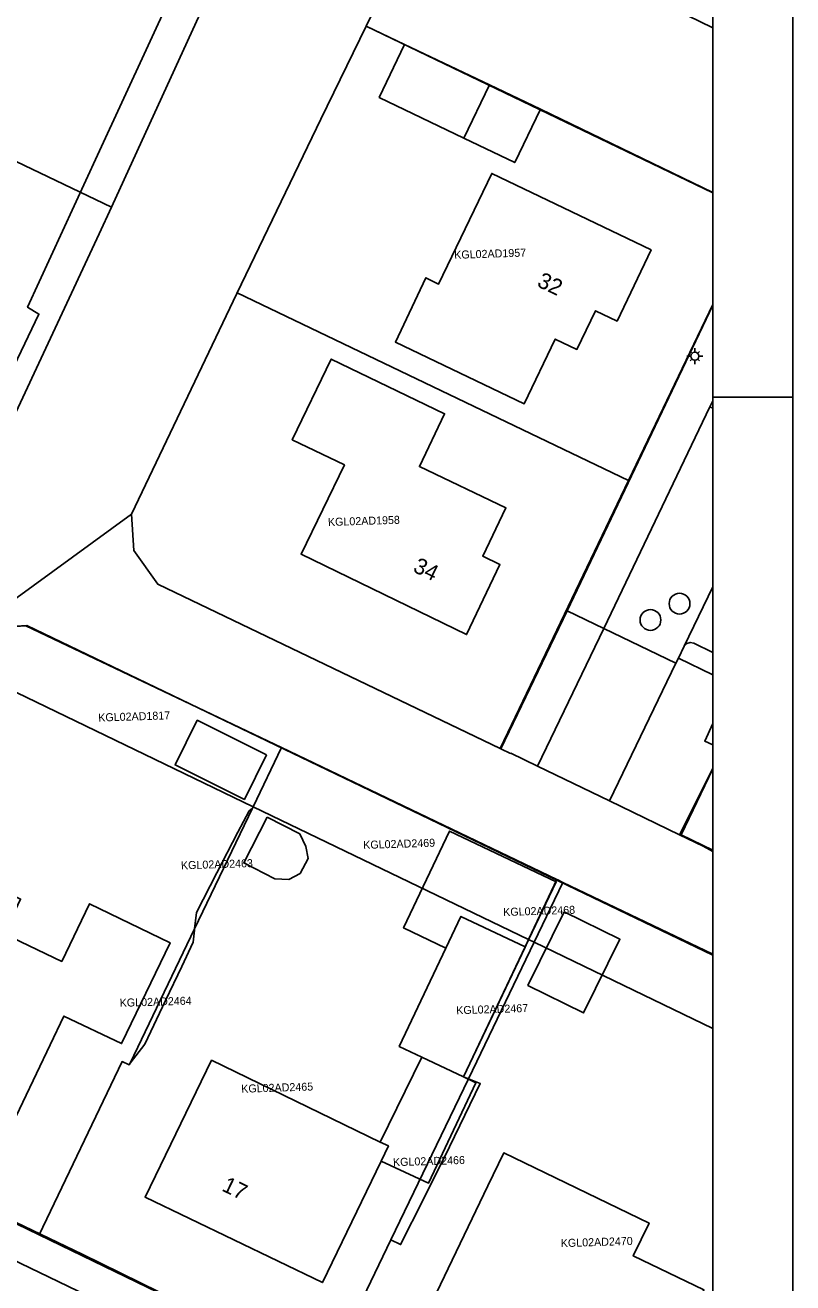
# Model space of a CAD drawing. Extents: x 124901 to 125496, y 515369 to 515789.
# Drawn here: x 125447.9 to 125495.9, y 515610.2 to 515688.8 of the extents above; entities that cross this region are included whole.
import ezdxf

# ---------------------------------------------------------------- set-up
doc = ezdxf.new("R2010")
doc.units = 0
for name, color, linetype in [('Alg Kaders', 7, 'Continuous'), ('Gebouw', 7, 'Continuous'), ('Lichtmast', 7, 'Continuous'), ('Luifel', 7, 'Continuous'), ('Onbegroeid terrein', 7, 'Continuous'), ('Parkeren', 7, 'Continuous'), ('Perceelnummers', 7, 'Continuous'), ('Perceelsgrenzen', 7, 'Continuous'), ('Putten', 7, 'Continuous'), ('Scheiding', 7, 'Continuous'), ('Teksten', 7, 'Continuous'), ('Vegetatie', 7, 'Continuous'), ('Voetpad', 7, 'Continuous'), ('Water', 7, 'Continuous'), ('Wegen drempel verkeerseiland', 7, 'Continuous'), ('Wegen lokale weg', 7, 'Continuous')]:
    doc.layers.add(name, color=color, linetype=linetype)

msp = doc.modelspace()

# ---------------------------------------------------------------- linework, layer by layer
at = {"layer": 'Alg Kaders'}
msp.add_line((125490.925, 515665.543), (125495.925, 515665.543), dxfattribs=at)
for points in [[(125495.925, 515789.043), (124901.425, 515789.043), (124901.425, 515368.543), (125495.925, 515368.543)], [(125490.925, 515784.043), (124906.425, 515784.043), (124906.425, 515373.543), (125490.925, 515373.543)]]:
    msp.add_lwpolyline(points, close=True, dxfattribs=at)
at = {"layer": 'Gebouw'}
for points in [[(125475.359, 515681.727), (125478.538, 515680.201), (125480.14, 515683.538), (125476.961, 515685.064)], [(125477.102, 515679.521), (125473.778, 515672.608), (125472.973, 515672.998), (125471.075, 515668.979), (125479.121, 515665.121), (125481.068, 515669.165), (125482.423, 515668.525), (125483.587, 515670.941), (125484.933, 515670.296), (125487.064, 515674.739)], [(125464.629, 515662.88), (125467.885, 515661.304), (125465.182, 515655.721), (125475.528, 515650.71), (125477.61, 515655.079), (125476.54, 515655.608), (125477.981, 515658.618), (125472.575, 515661.208), (125474.15, 515664.503), (125467.068, 515667.922)], [(125475.17, 515633.1), (125479.19, 515631.19), (125481.126, 515635.25), (125474.467, 515638.425), (125471.583, 515632.376), (125474.229, 515631.115)], [(125442.903, 515630.992), (125439.24, 515623.35), (125446.92, 515619.7), (125450.354, 515626.876), (125453.96, 515625.15), (125456.99, 515631.45), (125451.94, 515633.89), (125450.218, 515630.285), (125446.609, 515632.009), (125447.646, 515634.179), (125442.84, 515636.475), (125440.719, 515632.035)], [(125475.324, 515623.073), (125479.19, 515631.19), (125475.17, 515633.1), (125474.229, 515631.115), (125471.32, 515624.98), (125472.723, 515624.312)], [(125455.42, 515615.56), (125466.51, 515610.22), (125470.185, 515617.813), (125470.641, 515618.756), (125470.132, 515619.002), (125459.58, 515624.11)], [(125486.891, 515602.563), (125490.36, 515609.76), (125485.95, 515611.885), (125486.939, 515613.938), (125477.847, 515618.319), (125476.858, 515616.266), (125473.39, 515609.07), (125479.476, 515606.138), (125478.61, 515604.34), (125483.32, 515602.07), (125484.186, 515603.867)]]:
    msp.add_lwpolyline(points, close=True, dxfattribs=at)
at = {"layer": 'Lichtmast'}
for p, q in [((125489.585, 515668.313), (125489.515, 515668.384)), ((125489.797, 515668.401), (125489.797, 515668.601)), ((125490.009, 515668.313), (125490.08, 515668.385)), ((125489.497, 515668.102), (125489.297, 515668.101)), ((125489.585, 515667.889), (125489.513, 515667.818)), ((125489.797, 515667.801), (125489.797, 515667.601)), ((125490.009, 515667.889), (125490.079, 515667.818)), ((125490.097, 515668.101), (125490.297, 515668.101))]:
    msp.add_line(p, q, dxfattribs=at)
msp.add_circle((125489.797, 515668.101), 0.25, dxfattribs=at)
at = {"layer": 'Luifel'}
for points in [[(125471.651, 515687.572), (125470.065, 515684.268), (125475.359, 515681.727), (125476.961, 515685.064)], [(125463.023, 515643.201), (125458.691, 515645.354), (125457.303, 515642.561), (125461.635, 515640.408)], [(125463.051, 515639.31), (125461.596, 515636.445), (125463.541, 515635.457), (125464.413, 515635.406), (125465.122, 515635.784), (125465.625, 515636.713), (125465.484, 515637.469), (125465.106, 515638.256)], [(125481.636, 515633.389), (125479.363, 515628.787), (125482.843, 515627.068), (125485.116, 515631.67)], [(125475.324, 515623.073), (125472.723, 515624.312), (125470.132, 515619.002), (125470.641, 515618.756), (125470.185, 515617.813), (125473.135, 515616.423), (125476.095, 515622.706)]]:
    msp.add_lwpolyline(points, close=True, dxfattribs=at)
at = {"layer": 'Onbegroeid terrein'}
for points in [[(125490.925, 515630.677), (125448.027, 515651.268), (125444.728, 515651.073), (125443.321, 515649.329), (125433.556, 515627.939), (125431.85, 515627.386), (125429.766, 515628.208), (125428.663, 515630.094), (125436.481, 515646.34), (125445.451, 515665.509), (125446.119, 515665.186), (125448.787, 515670.727), (125448.083, 515671.163), (125452.441, 515680.669), (125457.131, 515690.833)], [(125490.925, 515678.324), (125480.14, 515683.538), (125478.538, 515680.201), (125475.359, 515681.727), (125476.961, 515685.064), (125471.651, 515687.572), (125469.241, 515688.71), (125466.419, 515682.908), (125461.167, 515672.009), (125454.573, 515658.231), (125454.714, 515655.957), (125456.22, 515653.859), (125477.672, 515643.566), (125481.808, 515652.185), (125490.925, 515671.289)], [(125490.925, 515642.348), (125488.834, 515638.195), (125490.31, 515637.482), (125490.925, 515637.15)], [(125375.169, 515609.812), (125392.301, 515615.845), (125406.232, 515620.771), (125414.095, 515623.452), (125417.469, 515624.564), (125420.516, 515625.062), (125421.795, 515625.138), (125423.115, 515625.058), (125424.478, 515624.722), (125427.773, 515623.362), (125434.165, 515620.296), (125439.534, 515617.72), (125451.494, 515611.999), (125464.767, 515605.477)]]:
    msp.add_lwpolyline(points, dxfattribs=at)
for points in [[(125473.778, 515672.608), (125477.102, 515679.521), (125487.064, 515674.739), (125484.933, 515670.296), (125483.587, 515670.941), (125482.423, 515668.525), (125481.068, 515669.165), (125479.121, 515665.121), (125471.075, 515668.979), (125472.973, 515672.998)], [(125467.885, 515661.304), (125464.629, 515662.88), (125467.068, 515667.922), (125474.15, 515664.503), (125472.575, 515661.208), (125477.981, 515658.618), (125476.54, 515655.608), (125477.61, 515655.079), (125475.528, 515650.71), (125465.182, 515655.721)], [(125479.19, 515631.19), (125475.324, 515623.073), (125472.723, 515624.312), (125471.32, 515624.98), (125474.229, 515631.115), (125471.583, 515632.376), (125474.467, 515638.425), (125481.126, 515635.25)], [(125439.24, 515623.35), (125442.903, 515630.992), (125440.719, 515632.035), (125442.84, 515636.475), (125447.646, 515634.179), (125446.609, 515632.009), (125450.218, 515630.285), (125451.94, 515633.89), (125456.99, 515631.45), (125453.96, 515625.15), (125450.354, 515626.876), (125446.92, 515619.7)], [(125466.51, 515610.22), (125455.42, 515615.56), (125459.58, 515624.11), (125470.132, 515619.002), (125470.641, 515618.756), (125470.185, 515617.813)], [(125490.36, 515609.76), (125486.891, 515602.563), (125484.186, 515603.867), (125483.32, 515602.07), (125478.61, 515604.34), (125479.476, 515606.138), (125473.39, 515609.07), (125476.858, 515616.266), (125477.847, 515618.319), (125486.939, 515613.938), (125485.95, 515611.885)]]:
    msp.add_lwpolyline(points, close=True, dxfattribs=at)
at = {"layer": 'Parkeren'}
msp.add_lwpolyline([(125490.925, 515653.689), (125489.138, 515649.978), (125489.291, 515650.147), (125489.509, 515650.219), (125489.734, 515650.175), (125490.925, 515649.58)], dxfattribs=at)
at = {"layer": 'Perceelsgrenzen'}
for points in [[(125453.316, 515677.409), (125424.5, 515691.221), (125432.811, 515708.356), (125432.874, 515708.485), (125461.248, 515694.727)], [(125417.983, 515677.745), (125422.606, 515687.317), (125424.5, 515691.221), (125453.316, 515677.409), (125452.553, 515675.743), (125446.912, 515663.647)], [(125477.618, 515643.592), (125456.22, 515653.859), (125454.714, 515655.957), (125454.573, 515658.231), (125461.167, 515672.009), (125461.189, 515672.055), (125485.649, 515660.326)], [(125443.053, 515649.181), (125444.658, 515651.051), (125447.978, 515651.259), (125460.02, 515645.53), (125463.963, 515643.642), (125462.19, 515639.955)], [(125458.523, 515632.331), (125454.483, 515623.931), (125454.428, 515623.816), (125453.982, 515624.032), (125448.8, 515613.204), (125432.377, 515621.151), (125427.879, 515623.328), (125430.488, 515629.198), (125432.962, 515634.284), (125438.238, 515645.132), (125440.645, 515650.271), (125440.672, 515650.329), (125443.053, 515649.181), (125462.19, 515639.955), (125462.144, 515639.859), (125461.924, 515639.69), (125461.215, 515638.361), (125459.902, 515635.812), (125458.642, 515633.35)], [(125463.963, 515643.642), (125481.177, 515635.398), (125479.405, 515631.655), (125462.19, 515639.955)], [(125466.757, 515604.514), (125464.319, 515605.693), (125448.8, 515613.204), (125453.982, 515624.032), (125454.428, 515623.816), (125454.483, 515623.931), (125455.417, 515625.125), (125456.7, 515627.855), (125457.727, 515629.976), (125458.438, 515631.48), (125458.516, 515632.25), (125458.523, 515632.331), (125462.144, 515639.859), (125462.19, 515639.955), (125479.405, 515631.655), (125479.182, 515631.185), (125475.333, 515623.083), (125475.644, 515622.957), (125470.796, 515612.896)], [(125462.144, 515639.859), (125458.523, 515632.331), (125458.642, 515633.35), (125459.902, 515635.812), (125461.215, 515638.361), (125461.924, 515639.69)], [(125479.405, 515631.655), (125481.177, 515635.398), (125481.222, 515635.377), (125481.552, 515635.219), (125479.754, 515631.487)], [(125454.483, 515623.931), (125458.523, 515632.331), (125458.516, 515632.25), (125458.438, 515631.48), (125457.727, 515629.976), (125456.7, 515627.855), (125455.417, 515625.125)], [(125475.333, 515623.083), (125479.182, 515631.185), (125479.405, 515631.655), (125479.754, 515631.487), (125475.644, 515622.957)], [(125470.796, 515612.896), (125475.644, 515622.957), (125476.384, 515622.659), (125474.464, 515618.705), (125472.827, 515615.436), (125471.395, 515612.594)]]:
    msp.add_lwpolyline(points, close=True, dxfattribs=at)
for points in [[(125461.248, 515694.727), (125453.316, 515677.409), (125452.553, 515675.743), (125446.912, 515663.647), (125440.672, 515650.329), (125443.053, 515649.181), (125444.658, 515651.051), (125447.978, 515651.259), (125460.02, 515645.53), (125463.963, 515643.642), (125481.177, 515635.398), (125481.222, 515635.377), (125481.552, 515635.219), (125490.925, 515630.741)], [(125490.925, 515671.32), (125485.649, 515660.326), (125477.618, 515643.592), (125456.22, 515653.859), (125454.714, 515655.957), (125454.573, 515658.231), (125461.167, 515672.009), (125461.189, 515672.055), (125466.419, 515682.908), (125469.241, 515688.71), (125490.925, 515678.313)], [(125490.925, 515671.32), (125485.649, 515660.326), (125461.189, 515672.055), (125466.419, 515682.908), (125469.241, 515688.71), (125490.925, 515678.313)], [(125490.925, 515637.232), (125488.933, 515638.19), (125490.925, 515642.325)], [(125490.925, 515637.232), (125488.933, 515638.19), (125490.925, 515642.325)], [(125490.925, 515626.101), (125479.754, 515631.487), (125481.552, 515635.219), (125490.925, 515630.741)], [(125490.925, 515599.424), (125488.337, 515594.082), (125483.848, 515596.248), (125466.757, 515604.514), (125470.796, 515612.896), (125471.395, 515612.594), (125472.827, 515615.436), (125474.464, 515618.705), (125476.384, 515622.659), (125475.644, 515622.957), (125479.754, 515631.487), (125490.925, 515626.101)], [(125464.319, 515605.693), (125448.8, 515613.204), (125432.377, 515621.151), (125427.879, 515623.328), (125424.074, 515614.767), (125423.088, 515612.915), (125352.068, 515590.151)]]:
    msp.add_lwpolyline(points, dxfattribs=at)
at = {"layer": 'Putten'}
for centre in [(125488.84, 515652.64), (125487.02, 515651.62)]:
    msp.add_circle(centre, 0.65, dxfattribs=at)
at = {"layer": 'Scheiding'}
msp.add_line((125490.925, 515642.348), (125488.834, 515638.195), dxfattribs=at)
at = {"layer": 'Vegetatie'}
for points in [[(125490.925, 515688.612), (125475.767, 515696.017), (125475.946, 515696.393), (125473.512, 515697.555), (125472.559, 515695.531), (125469.241, 515688.71), (125471.651, 515687.572), (125476.961, 515685.064), (125480.14, 515683.538), (125490.925, 515678.324)], [(125490.925, 515648.194), (125488.777, 515649.239), (125488.617, 515648.912), (125484.458, 515640.311), (125488.834, 515638.195), (125490.925, 515642.348)], [(125490.925, 515643.826), (125490.419, 515644.053), (125490.925, 515645.143)]]:
    msp.add_lwpolyline(points, dxfattribs=at)
for points in [[(125481.808, 515652.185), (125477.672, 515643.566), (125478.266, 515643.281), (125478.294, 515643.292), (125479.957, 515642.488), (125484.111, 515651.078)], [(125479.957, 515642.488), (125484.458, 515640.311), (125488.617, 515648.912), (125484.111, 515651.078)], [(125462.026, 515601.858), (125463.045, 515604.005), (125447.051, 515611.707), (125446.027, 515609.707), (125445.037, 515607.711), (125451.427, 515604.548), (125452.479, 515606.551)]]:
    msp.add_lwpolyline(points, close=True, dxfattribs=at)
at = {"layer": 'Voetpad'}
for points in [[(125490.925, 515691.099), (125476.732, 515698.039), (125476.551, 515697.66), (125475.946, 515696.393), (125475.767, 515696.017), (125490.925, 515688.612)], [(125490.925, 515671.289), (125481.808, 515652.185), (125484.111, 515651.078), (125490.741, 515664.936), (125490.925, 515665.321)], [(125490.925, 515649.58), (125489.734, 515650.175), (125489.509, 515650.219), (125489.291, 515650.147), (125489.138, 515649.978), (125488.777, 515649.239), (125490.925, 515648.194)], [(125490.925, 515645.143), (125490.419, 515644.053), (125490.925, 515643.826)], [(125464.767, 515605.477), (125451.494, 515611.999), (125439.534, 515617.72), (125434.165, 515620.296), (125427.773, 515623.362), (125424.478, 515624.722), (125423.115, 515625.058), (125421.795, 515625.138), (125420.516, 515625.062), (125417.469, 515624.564), (125414.095, 515623.452), (125406.232, 515620.771), (125392.301, 515615.845), (125375.169, 515609.812)], [(125378.669, 515608.861), (125389.667, 515612.721), (125396.869, 515615.238), (125407.837, 515619.085), (125415.182, 515621.683), (125418.603, 515622.78), (125419.985, 515622.996), (125421.168, 515623.076), (125422.437, 515623.018), (125423.967, 515622.72), (125425.93, 515621.968), (125427.838, 515621.112), (125431.321, 515619.424), (125435.239, 515617.475), (125439.775, 515615.327), (125444.402, 515613.086), (125447.051, 515611.707), (125463.045, 515604.005)]]:
    msp.add_lwpolyline(points, dxfattribs=at)
at = {"layer": 'Water'}
for points in [[(125457.131, 515690.833), (125452.441, 515680.669), (125448.083, 515671.163), (125448.787, 515670.727), (125446.119, 515665.186), (125445.451, 515665.509), (125436.481, 515646.34), (125428.663, 515630.094), (125429.766, 515628.208), (125431.85, 515627.386), (125433.556, 515627.939), (125443.321, 515649.329), (125444.728, 515651.073), (125454.573, 515658.231), (125461.167, 515672.009), (125466.419, 515682.908), (125469.241, 515688.71), (125472.559, 515695.531)], [(125484.458, 515640.311), (125479.957, 515642.488), (125478.294, 515643.292), (125478.266, 515643.281), (125477.672, 515643.566), (125456.22, 515653.859), (125454.714, 515655.957), (125454.573, 515658.231), (125444.728, 515651.073), (125448.027, 515651.268), (125490.925, 515630.677)], [(125490.925, 515637.15), (125490.31, 515637.482), (125488.834, 515638.195), (125484.458, 515640.311)]]:
    msp.add_lwpolyline(points, dxfattribs=at)
at = {"layer": 'Wegen drempel verkeerseiland'}
msp.add_lwpolyline([(125490.925, 515665.321), (125490.741, 515664.936), (125490.925, 515664.845)], dxfattribs=at)
at = {"layer": 'Wegen lokale weg'}
msp.add_lwpolyline([(125490.925, 515664.845), (125490.741, 515664.936), (125484.111, 515651.078), (125488.617, 515648.912), (125488.777, 515649.239), (125489.138, 515649.978), (125490.925, 515653.689)], dxfattribs=at)

# ---------------------------------------------------------------- texts
at = {"layer": 'Perceelnummers'}
for s, rotation, p in [('KGL02AD1957', 1.8336, (125474.76, 515674.183)), ('KGL02AD1958', 1.83351, (125466.866, 515657.488)), ('KGL02AD1817', 1.83334, (125452.505, 515645.272)), ('KGL02AD2469', 1.83353, (125469.069, 515637.313)), ('KGL02AD2463', 1.8334, (125457.676, 515636.037)), ('KGL02AD2468', 1.83364, (125477.821, 515633.121)), ('KGL02AD2464', 1.83336, (125453.846, 515627.448)), ('KGL02AD2467', 1.8336, (125474.886, 515626.982)), ('KGL02AD2465', 1.83344, (125461.445, 515622.08)), ('KGL02AD2466', 1.83356, (125470.933, 515617.492)), ('KGL02AD2470', 1.83368, (125481.422, 515612.434))]:
    msp.add_text(s, height=0.5, rotation=rotation, dxfattribs=at).set_placement(p)
at = {"layer": 'Teksten'}
for s, rotation, p in [('32', 334.4, (125479.869, 515672.493)), ('34', 334.2, (125472.112, 515654.669)), ('17', 334.3, (125460.163, 515615.987))]:
    msp.add_text(s, height=1, rotation=rotation, dxfattribs=at).set_placement(p)

doc.saveas('drawing.dxf')
